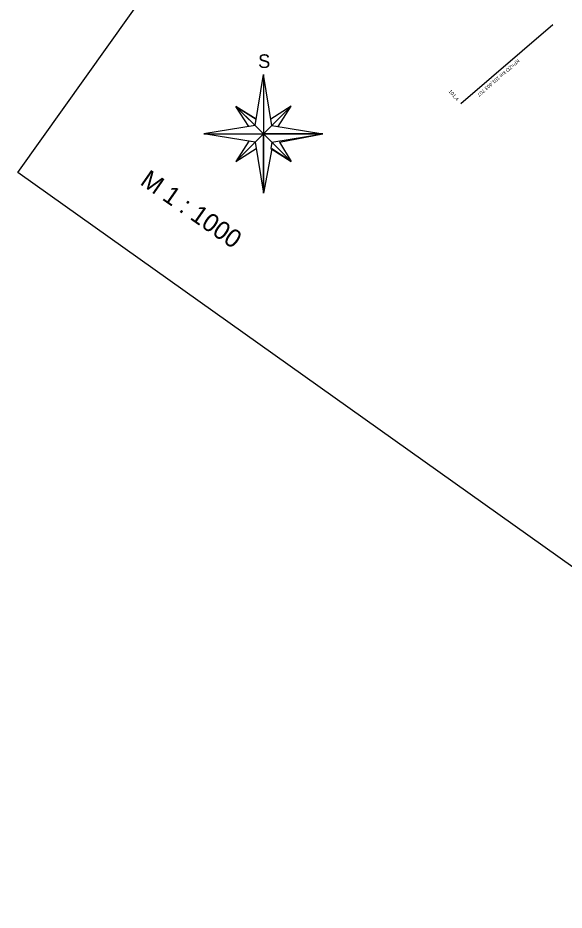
# Model space of a CAD drawing. Extents: x -505028 to -503155, y -1080361 to -1077947.
# Drawn here: x -504261.2 to -504080.9, y -1079577.5 to -1079282.8 of the extents above; entities that cross this region are included whole.
import ezdxf

# ---------------------------------------------------------------- set-up
doc = ezdxf.new("R2010")
doc.units = 0
for name, color, linetype in [('C3D-TRASA-POPIS', 7, 'Continuous'), ('C3D_Trasa-Popisy trasy', 7, 'Continuous'), ('Default', 7, 'Continuous'), ('POPIS', 7, 'Continuous'), ('Vrstva 53', 7, 'Continuous'), ('Vrstva 63', 7, 'Continuous')]:
    doc.layers.add(name, color=color, linetype=linetype)

# ---------------------------------------------------------------- blocks, each defined once
blk = doc.blocks.new('_U19')
at = {"layer": 'Default'}
for p, q in [((-178.7, -629.2), (178.7, 629.2)), ((-63.7, 114.2), (178.7, 629.2)), ((135.6, 146.5), (178.7, 629.2)), ((-34.5, 176.3), (-208.7, 374.2)), ((-208.7, 374.2), (-131.8, 122)), ((-208.7, 374.2), (0, 0)), ((374.2, 208.7), (0, 0)), ((135.6, 146.5), (374.2, 208.7)), ((374.2, 208.7), (182.7, 42.1)), ((-114.2, -63.7), (-629.2, 178.7)), ((-63.7, 114.2), (-629.2, 178.7)), ((-629.2, 178.7), (629.2, -178.7)), ((182.7, 42.1), (629.2, -178.7)), ((-374.2, -208.7), (0, 0)), ((-374.2, -208.7), (-176.3, -34.5)), ((-114.2, -63.7), (-178.7, -629.2)), ((208.7, -374.2), (0, 0)), ((-122, -131.8), (-374.2, -208.7)), ((63.7, -114.2), (-178.7, -629.2)), ((34.5, -176.3), (208.7, -374.2)), ((63.7, -114.2), (629.2, -178.7)), ((208.7, -374.2), (131.8, -122))]:
    blk.add_line(p, q, dxfattribs=at)
for points in [[(0, 0), (114.2, 63.7), (178.7, 629.2)], [(-208.7, 374.2), (-63.7, 114.2), (-34.5, 176.3)], [(374.2, 208.7), (114.2, 63.7), (176.3, 34.5)], [(0, 0), (-63.7, 114.2), (-629.2, 178.7)], [(-374.2, -208.7), (-114.2, -63.7), (-176.3, -34.5)], [(-178.7, -629.2), (0, 0), (-114.2, -63.7)], [(0, 0), (63.7, -114.2), (629.2, -178.7)], [(208.7, -374.2), (63.7, -114.2), (34.5, -176.3)]]:
    blk.add_lwpolyline(points, close=True, dxfattribs=at)
blk.add_text('S', height=150, rotation=74.14529, dxfattribs=at).set_placement((-713.9, 141.5))

msp = doc.modelspace()

# ---------------------------------------------------------------- linework, layer by layer
at = {"layer": 'C3D-TRASA-POPIS'}
msp.add_line((-504084.72, -1079285.12), (-504114.98, -1079311.28), dxfattribs=at)
at = {"layer": 'Vrstva 63'}
msp.add_lwpolyline([(-503746.76, -1079335.57), (-503919, -1079577.52), (-504261.16, -1079333.94), (-504088.92, -1079091.99)], close=True, dxfattribs=at)

# ---------------------------------------------------------------- block references
at = {"layer": 'POPIS', "xscale": 0.030000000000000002, "yscale": 0.030000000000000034, "rotation": -74.14528506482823}
msp.add_blockref('_U19', (-504180.13, -1079321.15), dxfattribs=at)

# ---------------------------------------------------------------- texts
at = {"layer": 'C3D-TRASA-POPIS'}
msp.add_text('KP=ZO km 101,403 707', height=1.2, rotation=220.849, dxfattribs=at).set_placement((-504096.27, -1079296.39))
at = {"layer": 'C3D_Trasa-Popisy trasy'}
msp.add_text('101,4', height=1.2, rotation=310.6586, dxfattribs=at).set_placement((-504119.16, -1079307.17))
at = {"layer": 'Vrstva 53'}
msp.add_text('M 1 : 1000', height=6, rotation=325.1015, dxfattribs=at).set_placement((-504221.17, -1079337.62))

doc.saveas('drawing.dxf')
